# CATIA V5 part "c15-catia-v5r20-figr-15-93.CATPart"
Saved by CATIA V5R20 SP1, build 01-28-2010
Part number: Part1
Bounding box of the stored display mesh (mm): x -52.43 to 60.529, y -25.631 to 32.893, z 0 to 4
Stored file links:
  D:\v5_r20\psrt_files_downloaded\c15\c15-catia-v5r20-figr-15-93.CATPart
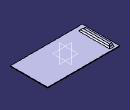
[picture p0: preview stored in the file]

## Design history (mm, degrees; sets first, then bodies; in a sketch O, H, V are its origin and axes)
SheetMetalParameters1: Thickness 1, BendRadius 5, KFactor 0.5 {= log(min(100,max(20*SheetMetalParameters1.BendRadius,SheetMetalParameters1.Thickness)/SheetMetalParameters1.Thickness))/log(100)/2}, ReliefRadialLength 1, ReliefAxialLength 2, MinimumBendRadius 0
Body1 (main body)
  Sketch1 on xy-plane, origin (0, 0, 0), H (1, 0, 0), V (0, 1, 0)
    line L1 (-52.4297, 32.8934) -> (60.5286, 32.8934)
    line L2 (60.5286, 32.8934) -> (60.5286, -25.6312)
    line L3 (60.5286, -25.6312) -> (-52.4297, -25.6312)
    line L4 (-52.4297, -25.6312) -> (-52.4297, 32.8934)
    horizontal: L1 H, L3 H
    vertical: L2 V, L4 V
  Wall1: Thickness 1, Profile Sketch1
  Sketch2 on face of Wall1, origin (0, 0, 1), H (1, 0, 0), V (0, 1, 0)
    line L1 (-47.3159, -16.5837) -> (-43.073, -16.5837)
    line L2 (-43.073, -16.5837) -> (-43.073, 26.788)
    line L3 (-43.073, 26.788) -> (-47.3159, 26.788)
    line L4 (-47.3159, 26.788) -> (-47.3159, -16.5837)
    horizontal: L1 H, L3 H
    vertical: L2 V, L4 V
  d_Stamp1: Stamp_FilletRadius 2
